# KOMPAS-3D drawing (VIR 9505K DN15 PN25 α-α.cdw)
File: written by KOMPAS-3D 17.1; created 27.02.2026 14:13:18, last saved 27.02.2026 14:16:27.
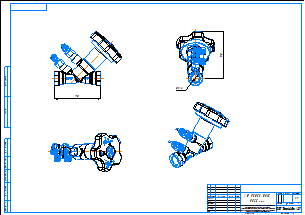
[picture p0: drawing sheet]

Sheet 1: A2, landscape

Title block, sheet 1: name: VIR 9505K DN15 / PN25 р-р; material: Внимание! Данный продукт является объектом авторского права ООО «Торговый Дом АДЛ». / Запрещается изменение, копирование, распространение / (в том числе путем копирования на другие сайты и ресурсы в Интернете) / или любое иное использование информации и объектов без предварительного / согласия правообладателя (ООО «Торговый Дом АДЛ»).; sheets: 1; organisation: ООО "Торговый дом АДЛ"; sheet format: A2

Views: Вид 1, Спереди, Проекционный вид 2, Проекционный вид 3, Вид 4, Изометрия
Referenced files in C:\Users\mipv\Desktop\VIR 9505K STP формат\: VIR 9505K DN15 PN25 р-р.m3d
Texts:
  adm
Dimensions and other numbers on the sheet: 90; 1:1; 1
